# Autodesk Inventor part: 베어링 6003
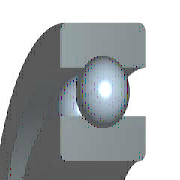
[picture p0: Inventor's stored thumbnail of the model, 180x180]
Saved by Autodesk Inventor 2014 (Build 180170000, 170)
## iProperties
Created: 2012-02
Part Number: 베어링 6003
Material: 강철, 연강
Description: 깊은 그루브 볼 베어링
Document SubType Name: Modeling
Standard: KS B 2023
Designer: mduedu
Standards Organization: KS
Language: ko-KR
Size Designation: 6003 - 17 x 35 x 10
Categories: <MemberInstance><Categories><Category DisplayName="샤프트 부품" InternalName="7f7aeb1f-a693-4053-b835-cee3144e0d98" Mnemonic="SHFT"><Category DisplayName="베어링" Inter
Density: 7.86 g/cm^3
Appearance: 터키옥색
Mass: 35.231 g
Surface Area: 48.7538 cm^2
Volume: 4.48231 cm^3
IsCustomPart: 1
Author: mduedu
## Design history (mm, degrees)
sketch "스케치" dims "d0" = 4.68 (= -0.26 x WD + 0.26 x BD)
  geometry: L1 (2.66, 13)-(7.34, 13); L2 (5, 13)-(5, 10.66); L3 (5, 13)-(5, 15.34); L4 (3.261, 11.434)-(0, 11.434); L5 (0, 8.5)-(10, 8.5); L6 (3.261, 14.566)-(0, 14.566); L7 (0, 17.5)-(10, 17.5); L8 (10, 8.5)-(10, 11.434); L9 (6.739, 11.434)-(10, 11.434); L10 (6.739, 14.566)-(10, 14.566); L11 (10, 17.5)-(10, 14.566); L12 (-1.4, 0)-(8.4, 0) reference; L13 (0, -0.3)-(0, 5.3) reference
  constraints: 22 end point, 4 point on line, 2 collinear, 2 perpendicular, 2 symmetric about line, 1 midpoint, 1 parallel, 14 other
  dimensions: "d9" = 17 diameter of L5 L12 (= WD); "d11" = 35 diameter of L7 L12 (= BD); "d12" = 10 distance between parallel lines of L8 L13 (= KB); "d13" = 22.868 diameter of L9 L12 (= 0.326 x BD + 0.674 x WD)
revolve "본체" stored, may be unused: angle "d6" = 90 deg
revolve "볼" stored, may be unused: angle "d7" = 90 deg
pattern_circular "IDS_ARRAYBALL[SIMPL:T]" dims angle "d3" = 360 deg
body "Solid1"
fillet "모깎기1" dims "d1" = 0.3 (= KRS)
other parameters: "WD" = 17 [user parameter; used in 5 equation terms], "BD" = 35 [user parameter; used in 5 equation terms], "KB" = 10 [user parameter; used in 1 equation term], "KRS" = 0.3 [user parameter; used in 1 equation term], "d4" = 0, "d5" = 0, "d8" = 0, "d14" = 0, "d15" = 0, "BBA" = 0 [user parameter], "BC0" = 3250000 [user parameter], "BC" = 6050000 [user parameter], "BR" = 17.5 (= 0.5 x BD) [user parameter], "WR" = 8.5 (= 0.5 x WD) [user parameter]
